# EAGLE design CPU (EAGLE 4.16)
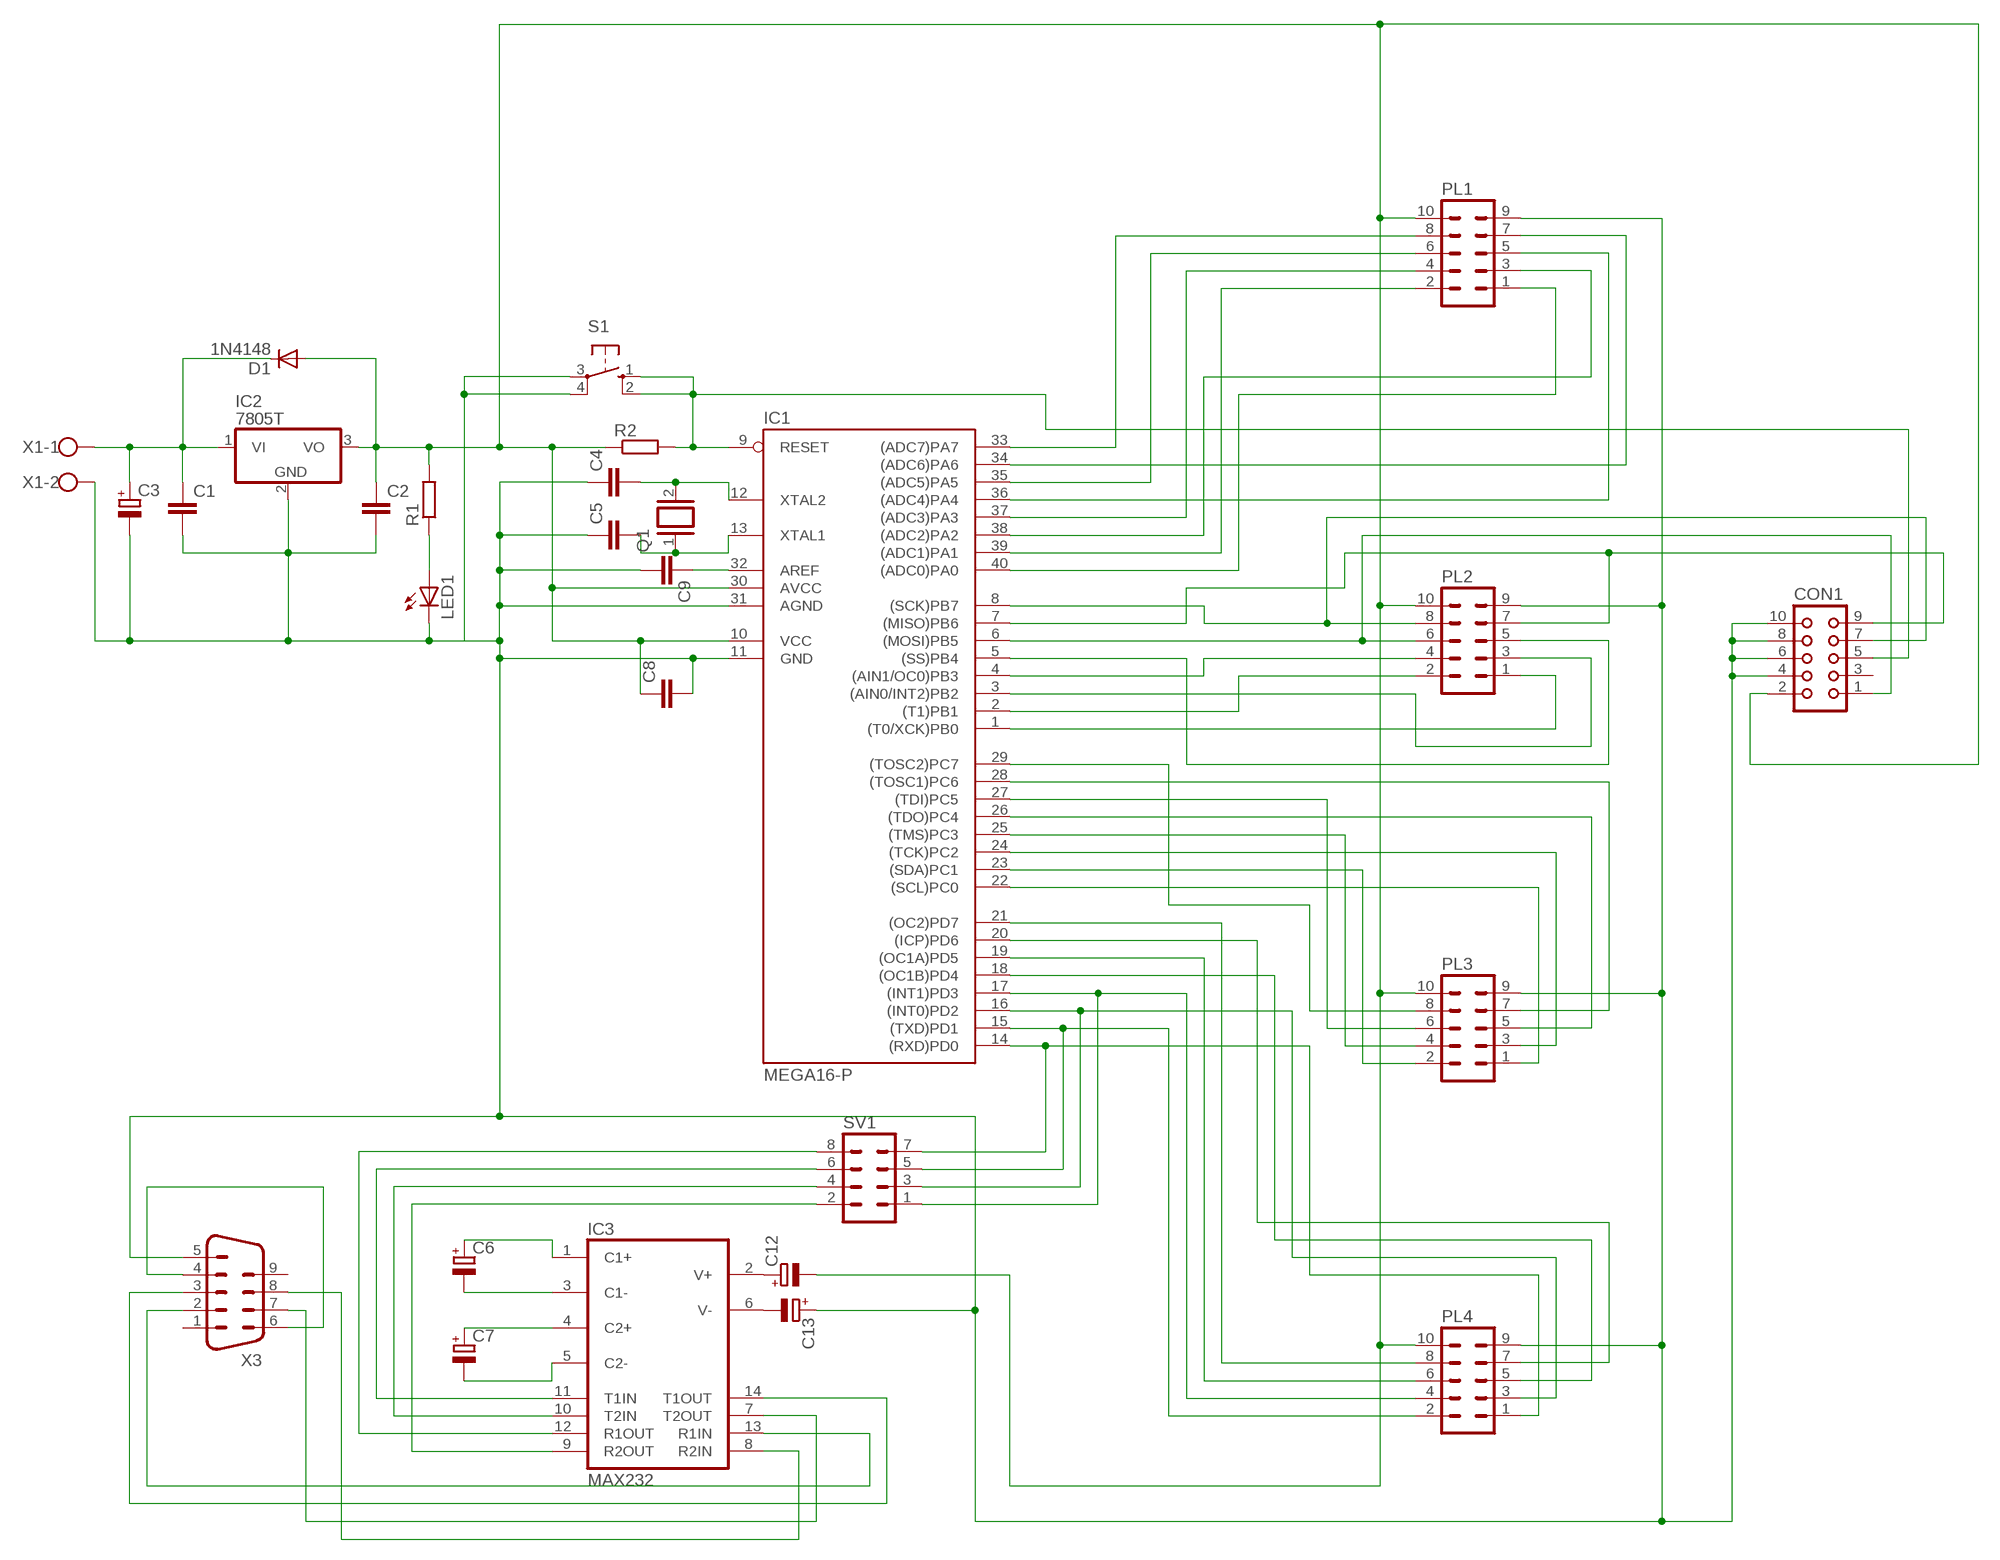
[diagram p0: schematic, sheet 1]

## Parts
C1  C7.5/5  [C7.5B5]
C2  C7.5/5  [C7.5B5]
C3  CPOL-EUE5-10.5  [E5-10,5]
C4  C5/3  [C5B3]
C5  C5/3  [C5B3]
C6  CPOL-EUE3.5-8  [E3,5-8]
C7  CPOL-EUE3.5-8  [E3,5-8]
C8  C2.5/4  [C2.5-4]
C9  C5/3  [C5B3]
C12  CPOL-EUE3.5-8  [E3,5-8]
C13  CPOL-EUE3.5-8  [E3,5-8]
CON1  CON10  [CON10]
D1  1N4148  [DO35-10]
IC1  MEGA16-P  [DIL40]
IC2  7805T  [TO220H]
IC3  MAX232  [DIL16]
LED1  LED3MM  [LED3MM]
PL1  10V  [10V]
PL2  10V  [10V]
PL3  10V  [10V]
PL4  10V  [10V]
Q1  XTAL  [Q]
R1  R-EU_0207/10  [0207/10]
R2  R-EU_0207/10  [0207/10]
S1  10-XX  [B3F-10XX]
SV1  MA04-2  [MA04-2]
X1  W237-102  [W237-102]
X3  M09H  [M09H]

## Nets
GND: C1.2 C2.2 C3.- C4.1 C5.1 C8.2 C9.2 C13.+ CON1.4 CON1.6 CON1.8 CON1.10 IC1.11(GND) IC1.31(AGND) IC2.2(GND) LED1.K(C) PL1.9 PL2.9 PL3.9 PL4.9 S1.3(P) S1.4(P1) X1.2 X3.5
N$1: C1.1 C3.+ D1.C IC2.1(VI) X1.1
N$2: CON1.5 IC1.9(RESET) R2.2 S1.1(S) S1.2(S1)
N$5: LED1.A R1.1
N$6: IC1.40((ADC0)PA0) PL1.1
N$7: IC1.39((ADC1)PA1) PL1.2
N$8: IC1.37((ADC3)PA3) PL1.4
N$9: IC1.35((ADC5)PA5) PL1.6
N$10: IC1.33((ADC7)PA7) PL1.8
N$11: IC1.38((ADC2)PA2) PL1.3
N$12: IC1.36((ADC4)PA4) PL1.5
N$13: IC1.34((ADC6)PA6) PL1.7
N$14: IC1.1((T0/XCK)PB0) PL2.1
N$15: IC1.2((T1)PB1) PL2.2
N$16: IC1.4((AIN1/OC0)PB3) PL2.4
N$17: CON1.1 IC1.6((MOSI)PB5) PL2.6
N$18: CON1.7 IC1.8((SCK)PB7) PL2.8
N$19: IC1.3((AIN0/INT2)PB2) PL2.3
N$20: IC1.5((SS)PB4) PL2.5
N$21: CON1.9 IC1.7((MISO)PB6) PL2.7
N$22: IC1.22((SCL)PC0) PL3.1
N$23: IC1.23((SDA)PC1) PL3.2
N$24: IC1.24((TCK)PC2) PL3.3
N$25: IC1.25((TMS)PC3) PL3.4
N$26: IC1.26((TDO)PC4) PL3.5
N$27: IC1.27((TDI)PC5) PL3.6
N$28: IC1.28((TOSC1)PC6) PL3.7
N$29: IC1.29((TOSC2)PC7) PL3.8
N$30: IC1.14((RXD)PD0) PL4.1 SV1.7
N$31: IC1.15((TXD)PD1) PL4.2 SV1.5
N$32: IC1.16((INT0)PD2) PL4.3 SV1.3
N$33: IC1.17((INT1)PD3) PL4.4 SV1.1
N$34: IC1.18((OC1B)PD4) PL4.5
N$35: IC1.19((OC1A)PD5) PL4.6
N$36: IC1.20((ICP)PD6) PL4.7
N$37: IC1.21((OC2)PD7) PL4.8
N$39: C5.2 IC1.13(XTAL1) Q1.1
N$40: C4.2 IC1.12(XTAL2) Q1.2
N$42: C12.+ IC3.2(V+)
N$43: C13.- IC3.6(V-)
N$44: X3.4 X3.6
N$45: IC3.12(R1OUT) SV1.8
N$46: IC3.11(T1IN) SV1.6
N$47: IC3.7(T2OUT) X3.7
N$48: IC3.8(R2IN) X3.8
N$49: IC3.10(T2IN) SV1.4
N$50: IC3.9(R2OUT) SV1.2
N$53: C9.1 IC1.32(AREF)
N$201: C6.- IC3.3(C1-)
N$202: C6.+ IC3.1(C1+)
N$203: C7.- IC3.5(C2-)
N$204: C7.+ IC3.4(C2+)
N$205: IC3.14(T1OUT) X3.3
N$206: IC3.13(R1IN) X3.2
VCC: C2.1 C8.1 C12.- CON1.2 D1.A IC1.10(VCC) IC1.30(AVCC) IC2.3(VO) PL1.10 PL2.10 PL3.10 PL4.10 R1.2 R2.1
Unconnected: CON1.3 X3.1 X3.9

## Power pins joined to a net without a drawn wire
GND: IC3.15(GND)
VCC: IC3.16(VCC)

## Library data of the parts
C1 C2 C4 C5 C8 C9 = capacitor-wima:C: CAPACITOR
C3 C6 C7 C12 C13 = rcl:CPOL-EU: POLARIZED CAPACITOR, European symbol
CON1 = con-harting:CON10: CONNECTOR
D1 = diode:1N4148: DIODE
IC1 = atmel:MEGA16-P: MICROCONTROLLER 16 Kbytes FLASH 1 kbytes SRAM 512 bytes EEPROM USART 8-channel 10 bit ADC Source: avr.lbr
IC2 = linear:78*: Positive VOLTAGE REGULATOR Source: http://cache.national.com/ds/LM/LM78L05.pdf http://www.fairchildsemi.com/ds/LM/LM7805.pdf
IC3 = maxim:MAX232: RS232 TRANSEIVER
LED1 = led:LED: LED
PL1-PL4 = con-harting-v:10V: CONNECTOR
Q1 = special:XTAL: CRYSTAL
R1 R2 = rcl:R-EU_: RESISTOR, European symbol
S1 = switch-omron:10-XX: OMRON SWITCH
SV1 = con-lstb:MA04-2: PIN HEADER
X1 = con-wago-500:W237-102: WAGO SCREW CLAMP
X3 = con-subd:M09: SUB-D

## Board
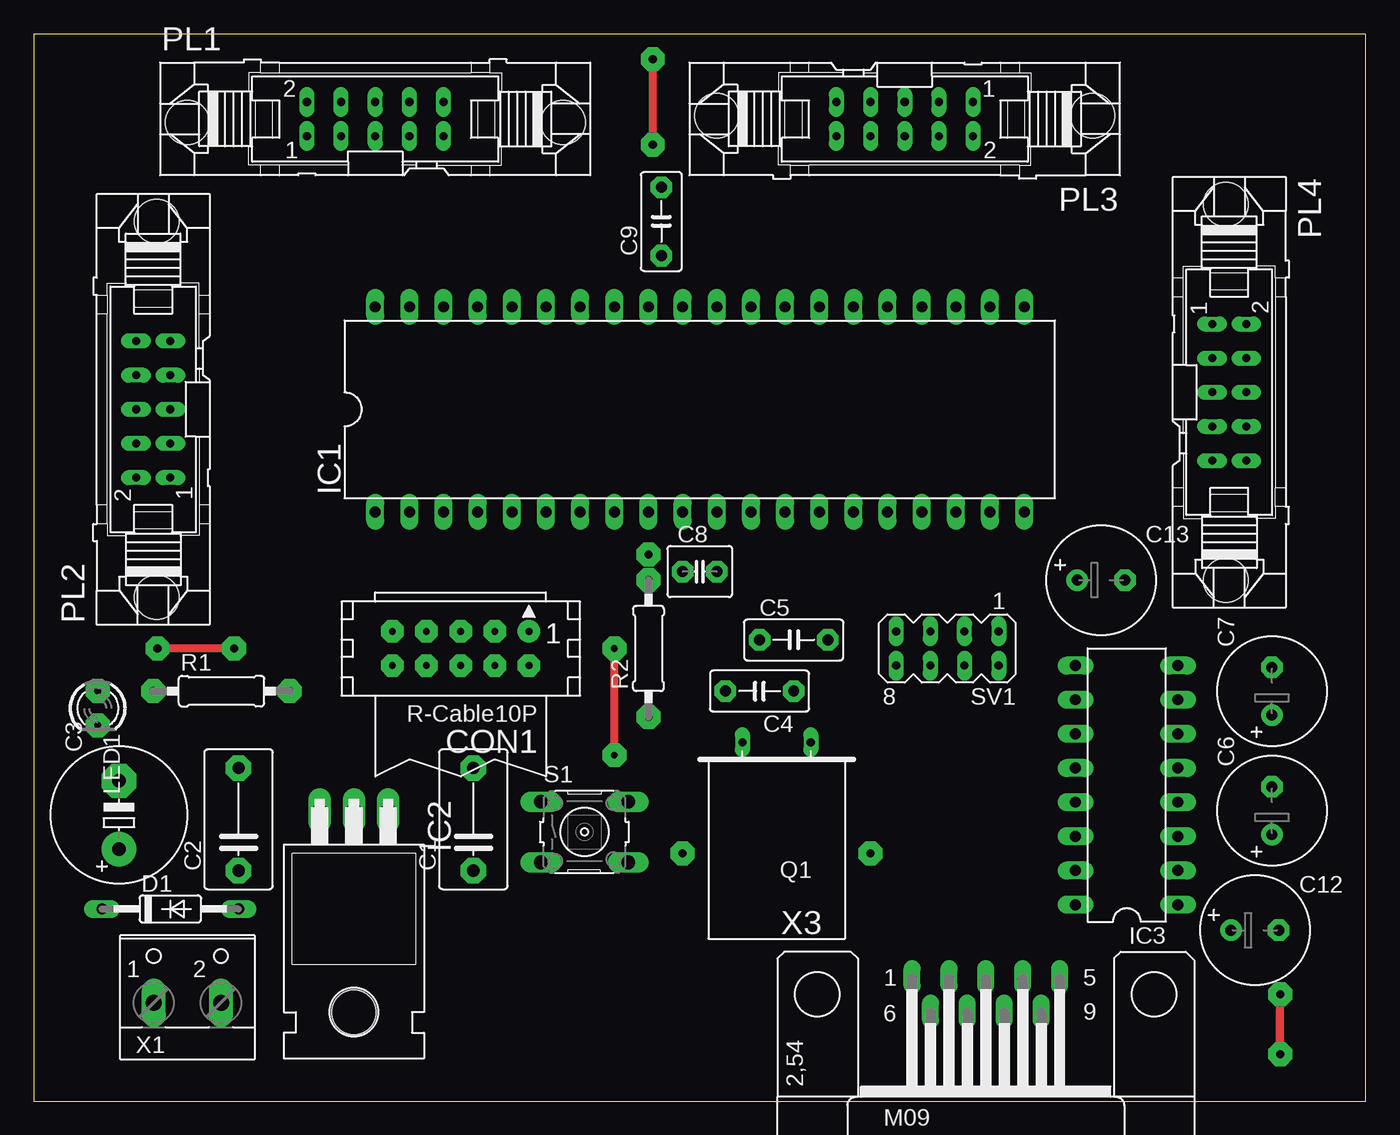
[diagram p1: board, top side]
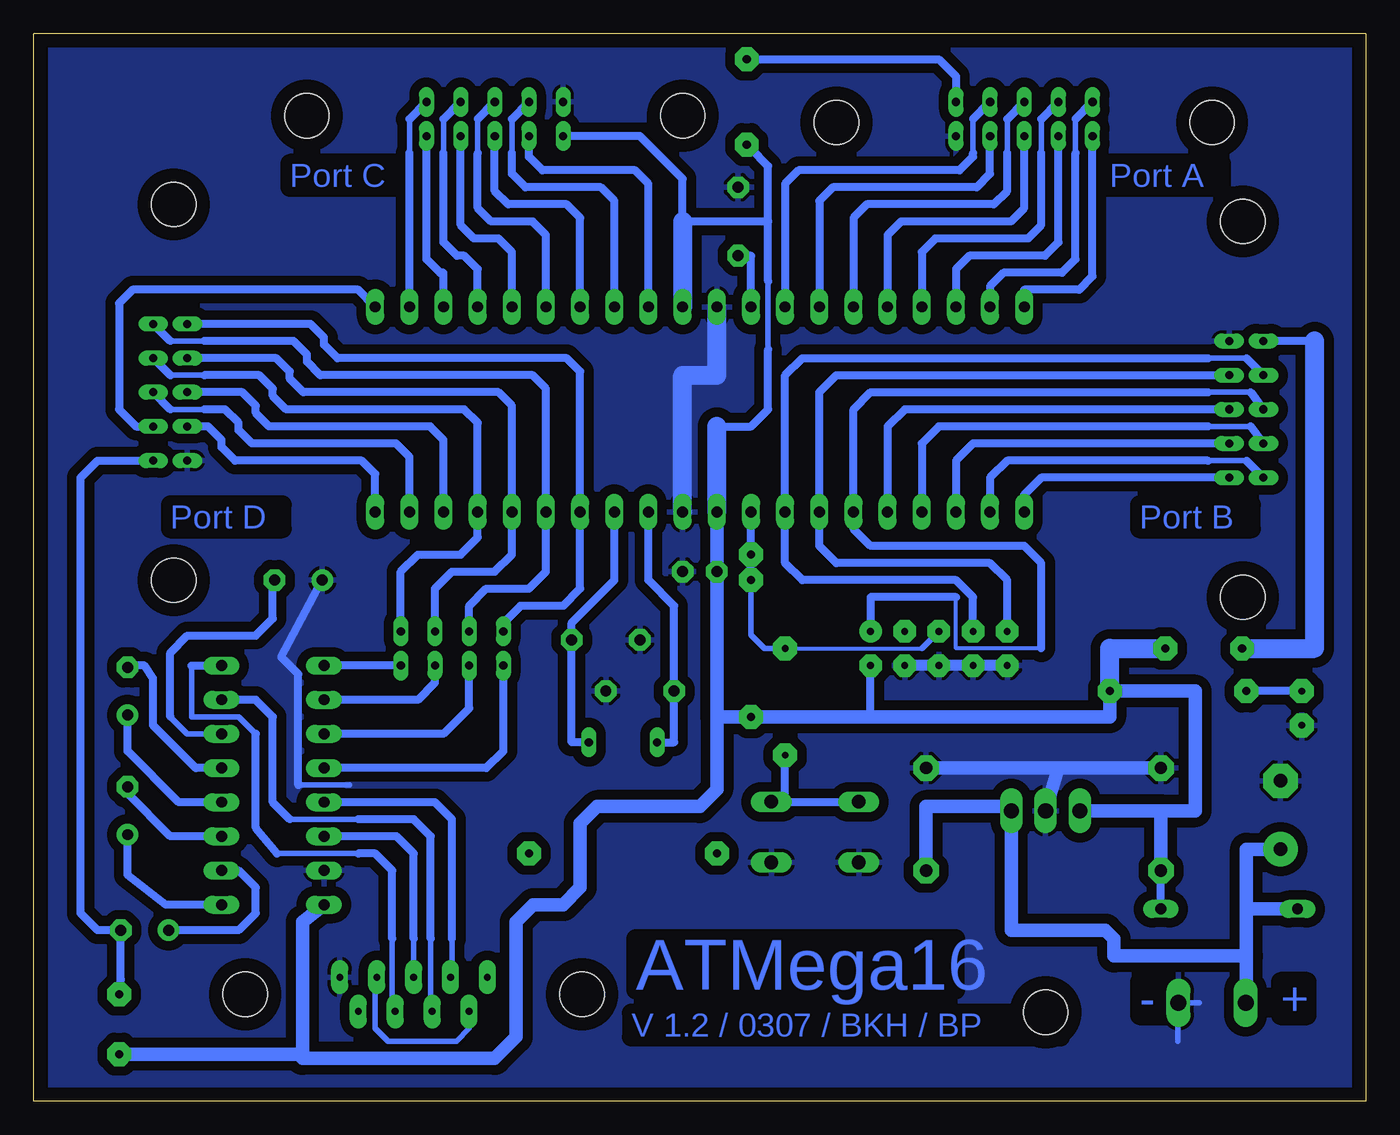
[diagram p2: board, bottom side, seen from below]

Size 99.06 x 79.38 mm. Coordinates in mm from the lower left corner, seen from the top.
Outline: 0,0 99.06,0 99.06,79.38 0,79.38 0,0
Copper layers (1*16): Top 0.035mm / dielectric 1.5mm / Bottom 0.035mm
Design rules "default": minimum track width 10mil, minimum drill 24mil, track to track 28mil, track to pad 28mil, pad to pad 10mil, via to via 10mil, smd to smd 8mil, copper to edge 40mil, drill to drill 8mil, minimum pad ring 10mil, minimum via ring 8mil, stop-mask expansion 4mil, vias tented up to drill 0mil, thermal gap 10mil

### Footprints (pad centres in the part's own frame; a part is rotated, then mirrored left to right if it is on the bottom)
C7.5B5 = drill 0.914 pad 1.905 octagon: 1 -3.81,0; 2 3.81,0
E5-10,5 = drill 1.016 pad 2.54 round: + -2.54,0 | drill 1.016 pad 2.54 octagon: - 2.54,0
C5B3 = drill 0.813 pad 1.6 octagon: 1 -2.54,0; 2 2.54,0
E3,5-8 = drill 0.813 pad 1.6 round: + -1.778,0 | drill 0.813 pad 1.6 octagon: - 1.778,0
C2.5-4 = drill 0.813 pad 1.6 octagon: 1 -1.27,0; 2 1.27,0
CON10 = drill 0.5 pad 1.676 round: 1 -5.08,-1.27 | drill 0.5 pad 1.676 octagon: 2 -5.08,1.27; 3 -2.54,-1.27; 4 -2.54,1.27; 5 0,-1.27; 6 0,1.27; 7 2.54,-1.27; 8 2.54,1.27; 9 5.08,-1.27; 10 5.08,1.27
DO35-10 = drill 0.813 long: A 5.08,0; C -5.08,0
DIL40 = drill 0.813 long: 1 -24.13,-7.62; 2 -21.59,-7.62; 3 -19.05,-7.62; 4 -16.51,-7.62; 5 -13.97,-7.62; 6 -11.43,-7.62; 7 -8.89,-7.62; 8 -6.35,-7.62; 9 -3.81,-7.62; 10 -1.27,-7.62; 11 1.27,-7.62; 12 3.81,-7.62; 13 6.35,-7.62; 14 8.89,-7.62; 15 11.43,-7.62; 16 13.97,-7.62; 17 16.51,-7.62; 18 19.05,-7.62; 19 21.59,-7.62; 20 24.13,-7.62; 21 24.13,7.62; 22 21.59,7.62; 23 19.05,7.62; 24 16.51,7.62; 25 13.97,7.62; 26 11.43,7.62; 27 8.89,7.62; 28 6.35,7.62; 29 3.81,7.62; 30 1.27,7.62; 31 -1.27,7.62; 32 -3.81,7.62; 33 -6.35,7.62; 34 -8.89,7.62; 35 -11.43,7.62; 36 -13.97,7.62; 37 -16.51,7.62; 38 -19.05,7.62; 39 -21.59,7.62; 40 -24.13,7.62
TO220H = drill 1.118 long: 1 -2.54,-10.16; 2 0,-10.16; 3 2.54,-10.16 | hole 3.302: 0,4.826
DIL16 = drill 0.813 long: 1 -8.89,-3.81; 2 -6.35,-3.81; 3 -3.81,-3.81; 4 -1.27,-3.81; 5 1.27,-3.81; 6 3.81,-3.81; 7 6.35,-3.81; 8 8.89,-3.81; 9 8.89,3.81; 10 6.35,3.81; 11 3.81,3.81; 12 1.27,3.81; 13 -1.27,3.81; 14 -3.81,3.81; 15 -6.35,3.81; 16 -8.89,3.81
LED3MM = drill 0.5 pad 1.778 octagon: A -1.27,0; K 1.27,0
10V = drill 0.6 pad 1.016 long: 1 -5.08,-1.27; 2 -5.08,1.27; 3 -2.54,-1.27; 4 -2.54,1.27; 5 0,-1.27; 6 0,1.27; 7 2.54,-1.27; 8 2.54,1.27; 9 5.08,-1.27; 10 5.08,1.27 | hole 3.302: 13.97,-0.254; -13.97,-0.254
Q = drill 0.61 long: 1 -2.54,-7.62; 2 2.54,-7.62
0207/10 = drill 0.6 pad 1.778 octagon: 1 -5.08,0; 2 5.08,0
B3F-10XX = drill 1.016 long: 1 -3.251,2.261; 2 3.251,2.261; 3 -3.251,-2.261; 4 3.251,-2.261
MA04-2 = drill 0.6 long: 1 -3.81,-1.27; 2 -3.81,1.27; 3 -1.27,-1.27; 4 -1.27,1.27; 5 1.27,-1.27; 6 1.27,1.27; 7 3.81,-1.27; 8 3.81,1.27
W237-102 = drill 1.194 long: 1 -2.5,-1.27; 2 2.5,-1.27
M09H = drill 0.5 pad 1.27 long: 1 -5.486,1.27; 2 -2.743,1.27; 3 0,1.27; 4 2.743,1.27; 5 5.486,1.27; 6 -4.115,-1.27; 7 -1.372,-1.27; 8 1.372,-1.27; 9 4.115,-1.27 | hole 3.302: 12.522,0; -12.522,0

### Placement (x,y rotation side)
C1  32.7,20.95 90 top
C2  15.24,20.95 90 top
C3  6.35,21.27 90 top
C4  53.98,30.48 180 top
C5  56.52,34.29 0 top
C6  92.08,21.59 90 top
C7  92.08,30.48 90 top
C8  49.53,39.37 0 top
C9  46.67,65.41 90 top
C12  90.81,12.7 0 top
C13  79.38,38.73 0 top
CON1  31.75,33.66 180 top
D1  10.16,14.29 0 top
IC1  49.53,51.44 0 top
IC2  23.81,11.43 180 top
IC3  81.28,23.5 90 top
LED1  4.76,29.21 270 top
PL1  25.4,73.03 0 top
PL2  8.89,51.44 90 top
PL3  64.77,73.03 180 top
PL4  88.9,52.7 270 top
Q1  55.24,19.05 180 top
R1  13.97,30.48 0 top
R2  45.72,33.66 90 top
S1  40.96,20 0 top
SV1  67.94,33.66 180 top
X1  11.43,8.57 0 top
X3  70.8,7.94 0 top

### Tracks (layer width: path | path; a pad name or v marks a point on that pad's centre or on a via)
GND
  Bottom 0.406: 75.56,23.5 79.38,23.5 | 12.38,7.3 X1.2 13.97,7.3 13.97,4.45
  Bottom 0.61: C13.+ 80.64,33.02 79.38,31.75 79.38,23.5
  Bottom 0.813: CON1.4 CON1.6 CON1.8 CON1.10
  Bottom 1.016: 22.86,24.77 IC2.2 | 22.86,24.77 C1.2 | C2.2 22.86,24.77
  Bottom 1.422: IC1.31 48.26,53.98 50.8,53.98 IC1.11
  pour Bottom: 0,0.95 98.11,0.95 98.11,81.6 0,81.6
N$1
  Bottom 1.016: C1.1 32.7,21.91 26.67,21.91 IC2.1 26.35,12.7 19.37,12.7 18.73,12.06 18.73,10.79 8.89,10.79 | C3.+ 8.89,18.73 8.89,14.29 | 8.89,10.79 8.89,14.29 | X1.1 8.89,7.34 8.89,10.79 | 8.89,14.29 D1.C
N$2  (via drill 0.5 pad 1.78, 0.6 pad 1.78)
  Top 0.61: v43.18,25.72 v43.18,33.66
  Bottom 0.305: v43.18,33.66 33.02,33.66
  Bottom 0.406: 33.02,33.66 CON1.5 | v43.18,33.66 44.72,33.66 45.72,34.66 R2.2
  Bottom 0.61: R2.2 v45.72,40.64 IC1.9 | 43.18,22.23 v43.18,25.72 | S1.2 44.17,22.23 43.18,22.23 | S1.1 37.74,22.23 43.18,22.23
N$3  (via drill 0.5 pad 1.78)
  other vias: 43.18,25.72
N$4  (via drill 0.6 pad 1.78)
  other vias: 48.26,18.41
N$5
  Bottom 0.61: LED1.A R1.1
N$6
  Bottom 0.61: PL1.1 20.32,61.33 21.32,60.33 25.4,60.33 IC1.40
N$7
  Bottom 0.406: 21.59,70.48 21.59,73.03
  Bottom 0.61: 21.59,73.03 PL1.2 | 21.59,70.48 21.59,62.59 22.59,61.59 26.94,61.59 27.94,60.59 IC1.39
N$8
  Bottom 0.406: 24.13,70.48 24.13,73.03
  Bottom 0.61: 24.13,73.03 PL1.4 | 24.13,70.48 24.13,65.14 25.13,64.14 32.02,64.14 33.02,63.13 IC1.37
N$9
  Bottom 0.406: 26.67,70.48 26.67,73.03
  Bottom 0.61: 26.67,73.03 PL1.6 | 26.67,70.48 26.67,67.67 27.67,66.67 37.1,66.67 38.1,65.67 IC1.35
N$10
  Bottom 0.406: 29.21,70.48 29.21,73.03
  Bottom 0.61: 29.21,73.03 PL1.8 | 29.21,70.48 29.21,70.22 30.21,69.22 42.18,69.22 43.18,68.22 IC1.33
N$11
  Bottom 0.61: PL1.3 22.86,63.87 23.86,62.87 29.48,62.87 30.48,61.87 IC1.38
N$12
  Bottom 0.61: PL1.5 25.4,66.41 26.4,65.41 34.56,65.41 35.56,64.41 IC1.36
N$13
  Bottom 0.61: PL1.7 27.94,68.94 28.94,67.94 39.64,67.94 40.64,66.94 IC1.34
N$14
  Bottom 0.61: PL2.1 24.13,46.35 25.4,45.09 IC1.1
N$15
  Bottom 0.406: 8.89,47.62 11.75,47.62
  Bottom 0.61: PL2.2 8.89,47.62 | IC1.2 27.94,46.35 26.67,47.62 11.75,47.62
N$16
  Bottom 0.406: 8.57,50.16 11.75,50.16
  Bottom 0.61: PL2.4 8.57,50.16 | 11.75,50.16 28.53,50.16 31.75,50.16 33.02,48.9 IC1.4
N$17
  Bottom 0.305: 30.48,37.47 30.48,33.66 24.13,33.66
  Bottom 0.406: 11.75,52.7 8.57,52.7
  Bottom 0.61: 8.57,52.7 PL2.6 | 11.75,52.7 34.88,52.7 36.83,52.7 38.1,51.44 IC1.6 38.1,42.55 36.83,41.27 25.4,41.27 24.13,40.01 24.13,33.66 | 30.48,37.47 36.83,37.47 CON1.1
N$18
  Bottom 0.406: 11.75,55.24 8.89,55.24
  Bottom 0.61: 8.89,55.24 PL2.8 | 11.75,55.24 40.59,55.24 41.91,55.24 43.18,53.98 IC1.8 43.18,40.01 41.91,38.73 30.48,38.73 29.21,37.47 CON1.7
N$19
  Bottom 0.61: IC1.3 30.48,47.62 29.21,48.9 PL2.3
N$20
  Bottom 0.61: PL2.5 32.02,51.44 34.29,51.44 35.56,50.16 IC1.5
N$21
  Bottom 0.61: PL2.7 37.73,53.98 39.37,53.98 40.64,52.7 IC1.7 40.64,41.27 39.37,40.01 27.94,40.01 26.67,38.73 CON1.9
N$22
  Bottom 0.406: 71.12,70.48 71.12,73.03
  Bottom 0.61: IC1.22 71.12,70.48 | 71.12,73.03 PL3.1
N$23
  Bottom 0.61: IC1.23 68.58,61.59 68.85,61.59 69.85,62.59 PL3.2
N$24
  Bottom 0.406: 68.58,70.48 68.58,73.03
  Bottom 0.61: IC1.24 66.04,61.87 67.04,62.87 67.58,62.87 68.58,63.87 68.58,70.48 | 68.58,73.03 PL3.3
N$25
  Bottom 0.61: IC1.25 63.5,63.13 64.5,64.14 66.31,64.14 67.31,65.14 PL3.4
N$26
  Bottom 0.406: 66.04,70.48 66.04,73.03
  Bottom 0.61: IC1.26 60.96,64.41 61.96,65.41 65.04,65.41 66.04,66.41 66.04,70.48 | 66.04,73.03 PL3.5
N$27
  Bottom 0.61: IC1.27 58.42,65.67 59.42,66.67 63.77,66.67 64.77,67.67 PL3.6
N$28
  Bottom 0.406: 63.5,70.48 63.5,73.03
  Bottom 0.61: IC1.28 55.88,66.94 56.88,67.94 62.5,67.94 63.5,68.94 63.5,70.48 | 63.5,73.03 PL3.7
N$29
  Bottom 0.61: IC1.29 53.34,68.22 54.34,69.22 61.23,69.22 62.23,70.22 PL3.8
N$30
  Bottom 0.61: PL4.1 78.47,57.78 77.47,56.78 77.47,56.24 76.47,55.24 59.42,55.24 58.42,54.24 IC1.14 58.42,38.1 59.69,36.83 62.87,36.83 64.14,35.56 SV1.7
N$31
  Bottom 0.406: 86.36,56.52 88.9,56.52
  Bottom 0.61: 86.36,56.52 79.74,56.52 78.74,55.52 78.74,54.98 77.74,53.98 61.96,53.98 60.96,52.98 IC1.15 60.96,39.37 62.23,38.1 65.41,38.1 66.67,36.83 SV1.5 | 88.9,56.52 PL4.2
N$32
  Bottom 0.61: PL4.3 81.01,55.24 80.01,54.24 80.01,53.7 79.01,52.7 64.5,52.7 63.5,51.7 IC1.16 63.5,40.64 64.77,39.37 67.94,39.37 69.22,38.1 SV1.3
N$33
  Bottom 0.406: 86.36,53.98 88.9,53.98
  Bottom 0.61: 86.36,53.98 82.28,53.98 81.28,52.98 81.28,52.44 80.28,51.44 67.04,51.44 66.04,50.44 IC1.17 66.04,41.91 67.31,40.64 70.48,40.64 71.75,39.37 SV1.1 | 88.9,53.98 PL4.4
N$34
  Bottom 0.61: IC1.18 68.58,49.16 69.58,50.16 81.55,50.16 82.55,51.16 82.55,51.7 83.55,52.7 PL4.5
N$35
  Bottom 0.406: 86.36,51.44 88.9,51.44
  Bottom 0.61: IC1.19 71.12,47.9 72.12,48.9 82.82,48.9 83.82,49.9 83.82,50.44 84.82,51.44 86.36,51.44 | 88.9,51.44 PL4.6
N$36
  Bottom 0.61: IC1.20 73.66,46.62 74.66,47.62 84.09,47.62 85.09,48.62 85.09,49.16 86.09,50.16 PL4.7
N$37
  Bottom 0.61: IC1.21 74.93,60.33 91.71,60.33 92.71,59.33 92.71,51.44 91.44,50.16 PL4.8
N$39
  Bottom 0.61: Q1.1 59.05,26.67 C5.2 59.05,35.56 55.88,38.73 IC1.13
N$40
  Bottom 0.61: Q1.2 51.44,26.67 C4.2 51.44,36.83 53.34,38.73 IC1.12
N$41  (via drill 0.6 pad 1.78)
  other vias: 62.23,18.41
N$42
  Bottom 0.61: IC3.2 83.82,17.14 82.55,15.88 82.55,13.97 83.82,12.7 C12.+
N$43
  Bottom 0.406: IC3.6 87.63,27.3 88.9,28.57
  Bottom 0.61: 88.9,28.57 88.9,33.34 87.63,34.61 82.55,34.61 81.28,35.88 81.28,38.73 C13.-
N$44
  Bottom 0.406: 73.66,9.09 73.66,5.4 72.71,4.45 67.63,4.45 66.67,5.4 66.67,6.67
  Bottom 0.61: 73.66,9.09 X3.4 | 66.67,6.67 X3.6
N$45
  Bottom 0.61: IC3.12 65.41,24.77 64.14,26.04 SV1.8
N$46
  Bottom 0.61: IC3.11 68.58,27.3 66.67,29.21 SV1.6
N$47
  Bottom 0.406: 74.93,20.95 80.01,20.95 | 69.53,6.67 69.53,12.06
  Bottom 0.61: 74.93,20.95 70.8,20.95 69.53,19.68 69.53,12.06 | 80.01,20.95 81.28,22.23 81.28,28.57 82.55,29.84 IC3.7 | X3.7 69.53,6.67
N$48
  Bottom 0.406: 87.31,32.38 87.31,28.57 83.82,28.57 82.55,27.3 | 74.93,18.41 80.96,18.41 | 72.39,6.67 72.39,12.06
  Bottom 0.61: 87.31,32.38 IC3.8 | 82.55,27.3 82.55,20.32 80.96,18.41 | 74.93,18.41 73.66,18.41 72.39,17.14 72.39,12.06 | X3.8 72.39,6.67
N$49
  Bottom 0.61: SV1.4 69.22,31.11 70.48,29.84 IC3.10
N$50
  Bottom 0.61: SV1.2 IC3.9
N$53
  Bottom 0.61: IC1.32 45.72,62.87 C9.1
N$201
  Bottom 0.61: IC3.3 88.9,19.68 92.08,22.86 C6.- 92.08,23.5
N$202
  Bottom 0.61: IC3.1 89.22,14.61 92.08,16.83 C6.+
N$203
  Bottom 0.61: C7.- 92.08,32.38 90.81,32.38 90.17,31.43 90.17,27.94 87,24.77 IC3.5
N$204
  Bottom 0.61: IC3.4 88.27,22.23 92.08,26.04 C7.+
N$205
  Bottom 0.406: X3.3 70.8,12.06
  Bottom 0.61: X3.3 70.48,9.21 | IC3.14 72.07,19.68 70.8,18.41 70.8,12.06
N$206
  Bottom 0.406: 67.94,9.21 67.94,12.06
  Bottom 0.61: IC3.13 69.22,22.23 67.94,20.95 67.94,12.06 | X3.2 67.94,9.21
VCC  (via drill 0.6 pad 1.78)
  Top 0.61: v14.92,33.66 v9.21,33.66 | v92.71,3.49 v92.71,7.94 | v46.04,71.12 v46.04,77.47
  Bottom 0.406: 44.45,55.88 44.45,60.96 | 79.06,3.17 79.06,3.49
  Bottom 0.61: C8.1 IC1.10 | D1.A C2.1 | 48.26,50.16 45.72,50.16 44.45,51.44 44.45,55.88 | 44.45,60.96 44.45,65.41 | 44.45,65.41 50.8,65.41 50.8,68.58 53.98,71.75 PL3.10 | 3.81,56.52 PL2.10 | C12.- 92.71,12.7 | 36.83,28.57 CON1.2 | C12.- 92.58,9.02 v92.71,7.94 | C12.- 94.3,12.7 95.57,13.97 95.57,46.35 94.3,47.62 PL4.10 | v46.04,77.47 31.75,77.47 30.48,76.2 PL1.10 | v46.04,71.12 46.04,70.8 45.72,70.8 44.45,69.53 44.45,65.41
  Bottom 1.016: C2.1 15.24,21.59 IC2.3 12.7,21.59 12.7,28.57 | 48.26,28.57 C8.1 IC1.10 | 48.26,28.57 R2.1 36.83,28.57 19.05,28.57 R1.2 12.7,30.48 12.7,28.57 | 12.7,28.57 12.7,29.21 | IC3.16 79.06,13.34 79.06,3.49 v92.71,3.49 | 79.06,3.17 64.77,3.17 63.18,4.76 63.18,13.34 61.91,14.61 59.69,14.61 58.42,15.88 58.42,20.64 57.15,21.91 49.53,21.91 48.26,23.18 48.26,28.57
  Bottom 1.422: 50.8,65.41 IC1.30 | IC1.10 48.26,50.16 | 3.81,56.52 3.81,33.66 v9.21,33.66 | v14.92,33.66 19.05,33.66 R1.2

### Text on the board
Bottom: Port A | Port C | Port B | Port D | ATMega16 | + | - | V 1.2 / 0307 / BKH / BP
